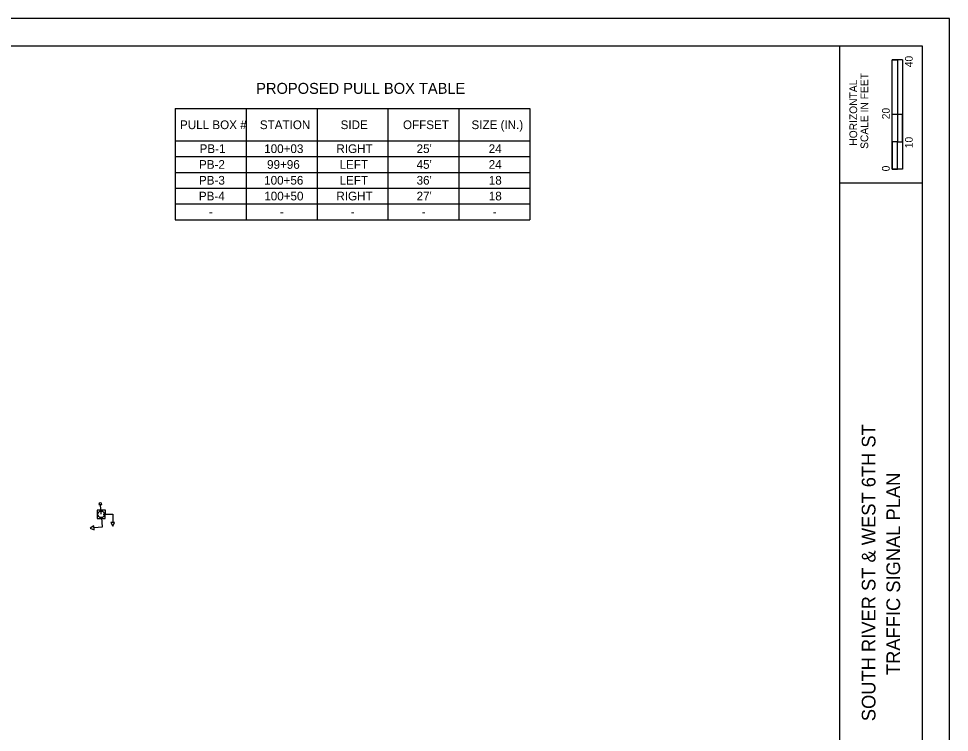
# Model space of a CAD drawing. Extents: x -32.9 to 34, y 0 to 22.3.
# Drawn here: x 17 to 34, y 8.96 to 22 of the extents above; entities that cross this region are included whole.
import ezdxf

# ---------------------------------------------------------------- set-up
doc = ezdxf.new("R2010")
doc.units = 0
for name, color, linetype in [('DT_X_Contour_Minor', 7, 'Continuous'), ('GE_P_Alignment', 7, 'Continuous'), ('GE_P_Driveway_CL', 7, 'Continuous'), ('PF_X_Ground_Line', 7, 'Continuous'), ('PV_P_Curb_Ramp', 7, 'Continuous'), ('PV_P_Saw_Cut_Line', 7, 'Continuous'), ('PV_P_Walk', 7, 'Continuous')]:
    doc.layers.add(name, color=color, linetype=linetype)

msp = doc.modelspace()

# ---------------------------------------------------------------- linework, layer by layer
at = {"layer": 'DT_X_Contour_Minor'}
msp.add_lwpolyline([(18.432, 12.873), (18.582, 12.871), (18.584, 13.021), (18.434, 13.023)], close=True, dxfattribs=at)
msp.add_circle((18.508, 12.947), 0.06, dxfattribs=at)
at = {"layer": 'GE_P_Alignment'}
msp.add_lwpolyline([(0, 0), (34, 0), (34, 22), (0, 22)], close=True, dxfattribs=at)
at = {"layer": 'GE_P_Driveway_CL'}
for p, q in [((18.483, 12.948), (18.483, 12.948)), ((18.508, 12.947), (18.508, 12.947))]:
    msp.add_line(p, q, dxfattribs=at)
for points in [[(18.543, 12.949), (18.718, 12.95), (18.719, 12.8)], [(18.513, 12.888), (18.528, 12.713), (18.379, 12.7)]]:
    msp.add_lwpolyline(points, dxfattribs=at)
for points in [[(18.754, 12.8), (18.684, 12.8), (18.719, 12.73)], [(18.382, 12.666), (18.376, 12.735), (18.309, 12.694)]]:
    msp.add_lwpolyline(points, close=True, dxfattribs=at)
at = {"layer": 'PF_X_Ground_Line'}
for p, q in [((19.859, 20.356), (26.337, 20.356)), ((19.859, 20.356), (19.859, 18.328)), ((21.155, 20.356), (21.155, 18.328)), ((22.45, 20.356), (22.45, 18.328)), ((23.746, 20.356), (23.746, 18.328)), ((25.042, 20.356), (25.042, 18.328)), ((26.337, 20.356), (26.337, 18.328)), ((19.859, 19.768), (26.337, 19.768)), ((19.859, 19.48), (26.337, 19.48)), ((19.859, 19.192), (26.337, 19.192)), ((19.859, 18.904), (26.337, 18.904)), ((19.859, 18.616), (26.337, 18.616)), ((19.859, 18.328), (26.337, 18.328))]:
    msp.add_line(p, q, dxfattribs=at)
at = {"layer": 'PV_P_Curb_Ramp'}
for p, q in [((32, 0.5), (32, 21.5)), ((32, 19), (33.5, 19))]:
    msp.add_line(p, q, dxfattribs=at)
msp.add_lwpolyline([(1.5, 21.5), (33.5, 21.5), (33.5, 0.5), (1.5, 0.5)], close=True, dxfattribs=at)
at = {"layer": 'PV_P_Saw_Cut_Line'}
for p, q in [((32.957, 19.25), (32.957, 21.25)), ((33.144, 21.25), (32.957, 21.25)), ((32.957, 20.25), (32.957, 21.25)), ((32.957, 21.25), (33.05, 21.25)), ((33.05, 21.25), (33.051, 21.25)), ((33.051, 21.25), (33.051, 20.25)), ((33.144, 21.25), (33.144, 19.25)), ((33.051, 20.25), (32.957, 20.25)), ((33.143, 20.25), (33.05, 20.25)), ((33.05, 20.25), (33.05, 19.75)), ((33.143, 19.75), (33.143, 20.25)), ((33.05, 19.75), (32.957, 19.75)), ((32.957, 19.75), (32.957, 19.25)), ((33.05, 19.25), (33.05, 19.75)), ((33.05, 19.75), (33.143, 19.75)), ((33.144, 19.25), (32.957, 19.25)), ((32.957, 19.25), (33.05, 19.25))]:
    msp.add_line(p, q, dxfattribs=at)
at = {"layer": 'PV_P_Walk'}
for p, q in [((18.465, 13.124), (18.521, 13.129)), ((18.508, 12.947), (18.493, 13.127))]:
    msp.add_line(p, q, dxfattribs=at)
msp.add_arc((18.493, 13.127), 0.028, 4.8822, 184.8818, dxfattribs=at)

# ---------------------------------------------------------------- texts
at = {"layer": 'PF_X_Ground_Line'}
msp.add_text('PROPOSED PULL BOX TABLE', height=0.2, dxfattribs=at).set_placement((21.339, 20.626))
for s, p in [('PULL BOX #', (19.948, 19.982)), ('STATION', (21.406, 19.982)), ('SIDE', (22.881, 19.982)), ('OFFSET', (24.02, 19.982)), ('SIZE (IN.)', (25.271, 19.982)), ('PB-1', (20.305, 19.545)), ('100+03', (21.486, 19.545)), ('RIGHT', (22.804, 19.545)), ("25'", (24.269, 19.545)), ('24', (25.586, 19.545)), ('PB-2', (20.295, 19.257)), ('99+96', (21.538, 19.257)), ('LEFT', (22.862, 19.257)), ("45'", (24.269, 19.257)), ('24', (25.586, 19.257)), ('PB-3', (20.294, 18.968)), ('100+56', (21.485, 18.968)), ('LEFT', (22.862, 18.968)), ("36'", (24.269, 18.968)), ('18', (25.588, 18.968)), ('PB-4', (20.292, 18.68)), ('100+50', (21.487, 18.68)), ('RIGHT', (22.804, 18.68)), ("27'", (24.269, 18.68)), ('18', (25.588, 18.68)), ('-', (20.476, 18.392)), ('-', (21.771, 18.392)), ('-', (23.067, 18.392)), ('-', (24.363, 18.392)), ('-', (25.659, 18.392))]:
    msp.add_text(s, height=0.159, rotation=360, dxfattribs=at).set_placement(p)
at = {"layer": 'PV_P_Saw_Cut_Line'}
for s, height, p in [('40', 0.14, (33.33, 21.112)), ('SCALE IN FEET', 0.14, (32.517, 19.621)), ('HORIZONTAL', 0.14, (32.315, 19.679)), ('20', 0.14, (32.91, 20.162)), ('10', 0.14, (33.33, 19.633)), ('0', 0.14, (32.91, 19.211)), ('SOUTH RIVER ST & WEST 6TH ST', 0.25, (32.65, 9.169)), ('TRAFFIC SIGNAL PLAN', 0.25, (33.1, 10.011))]:
    msp.add_text(s, height=height, rotation=90, dxfattribs=at).set_placement(p)

doc.saveas('drawing.dxf')
